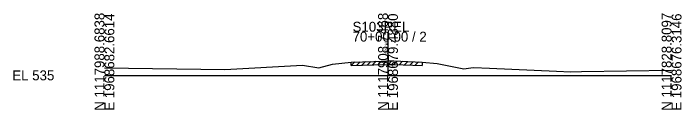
# Model space of a CAD drawing. Extents: x -26 to 163, y -10 to 24518.
# Drawn here: x -25.7 to 162.8, y 18490.3 to 18517.5 of the extents above; entities that cross this region are included whole.
import ezdxf

# ---------------------------------------------------------------- set-up
doc = ezdxf.new("R2010")
doc.units = 0
for name, color, linetype in [('RD_GPK_XS_Cell', 7, 'Continuous'), ('RD_XS_ExGround', 7, 'Continuous'), ('RD_XS_ExPaveRet', 7, 'Continuous'), ('RD_XS_TX_Elev_EX', 7, 'Continuous')]:
    doc.layers.add(name, color=color, linetype=linetype)

msp = doc.modelspace()

# ---------------------------------------------------------------- linework, layer by layer
at = {"layer": 'RD_GPK_XS_Cell'}
for p, q in [((80, 18500), (80, 18512.34)), ((0, 18500), (80, 18500)), ((80, 18500), (160, 18500))]:
    msp.add_line(p, q, dxfattribs=at)
at = {"layer": 'RD_XS_ExGround'}
msp.add_lwpolyline([(0, 18502.15), (33.98, 18501.68), (55.86, 18502.84), (60.51, 18502.13), (64.34, 18503.21), (69.63, 18503.74), (75.97, 18503.96), (80.14, 18504.11), (81.66, 18504.06), (89.61, 18503.77), (93.87, 18503.39), (101.36, 18501.89), (103.33, 18502.1), (104.26, 18502.2), (108.59, 18502.02), (127.49, 18501.22), (131.62, 18501.04), (134.56, 18501.08), (160, 18501.47)], dxfattribs=at)
at = {"layer": 'RD_XS_ExPaveRet'}
for p, q in [((69.63, 18502.74), (70.67, 18503.78)), ((69.63, 18502.74), (69.63, 18503.74)), ((69.63, 18502.74), (75.97, 18502.96)), ((71.13, 18502.79), (72.17, 18503.83)), ((72.63, 18502.85), (73.67, 18503.88)), ((74.13, 18502.9), (75.17, 18503.94)), ((75.63, 18502.95), (76.67, 18503.99)), ((75.97, 18502.96), (80.14, 18503.11)), ((77.13, 18503.01), (78.17, 18504.04)), ((78.63, 18503.06), (79.67, 18504.1)), ((80.13, 18503.11), (81.1, 18504.08)), ((80.14, 18503.11), (81.66, 18503.06)), ((81.63, 18503.06), (82.6, 18504.03)), ((81.66, 18503.06), (89.61, 18502.77)), ((83.13, 18503.01), (84.1, 18503.97)), ((84.63, 18502.95), (85.6, 18503.92)), ((86.13, 18502.9), (87.1, 18503.86)), ((87.63, 18502.84), (88.6, 18503.81)), ((89.61, 18503.77), (89.61, 18502.77))]:
    msp.add_line(p, q, dxfattribs=at)

# ---------------------------------------------------------------- texts
at = {"layer": 'RD_GPK_XS_Cell'}
for s, p in [('N 1117988.6838', (0, 18490)), ('E 1968682.6614', (2.8, 18490)), ('N 1117908.7468', (80, 18490)), ('E 1968679.4880', (82.8, 18490)), ('N 1117828.8097', (160, 18490)), ('E 1968676.3146', (162.8, 18490))]:
    msp.add_text(s, height=2.8, rotation=90, dxfattribs=at).set_placement(p)
for s, p in [('S103REL', (70, 18512.34)), ('70+00.00 / 2', (70, 18509.54)), ('EL 535', (-26, 18498.6))]:
    msp.add_text(s, height=2.8, dxfattribs=at).set_placement(p)
at = {"layer": 'RD_XS_TX_Elev_EX'}
msp.add_text('539.11', height=0.8, rotation=90, dxfattribs=at).set_placement((79.9, 18506.11))

doc.saveas('drawing.dxf')
